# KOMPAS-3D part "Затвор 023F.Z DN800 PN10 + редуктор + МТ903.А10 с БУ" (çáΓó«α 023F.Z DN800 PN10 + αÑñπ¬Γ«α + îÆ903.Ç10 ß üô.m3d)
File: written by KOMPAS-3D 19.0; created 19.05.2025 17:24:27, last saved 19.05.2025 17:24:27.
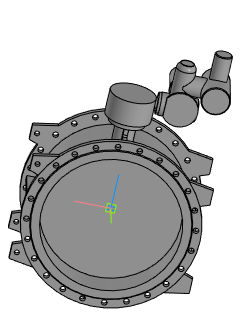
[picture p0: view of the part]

Document properties: Полное имя файла: Затвор 023F.Z DN800 PN10 + редуктор + МТ903.А10 с БУ.a3d

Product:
- Part/product: Затвор 023F.Z DN800 PN10 + редуктор + МТ903.А10 с БУ
    Масса: 874.939

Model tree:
1. Операция без истории:1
